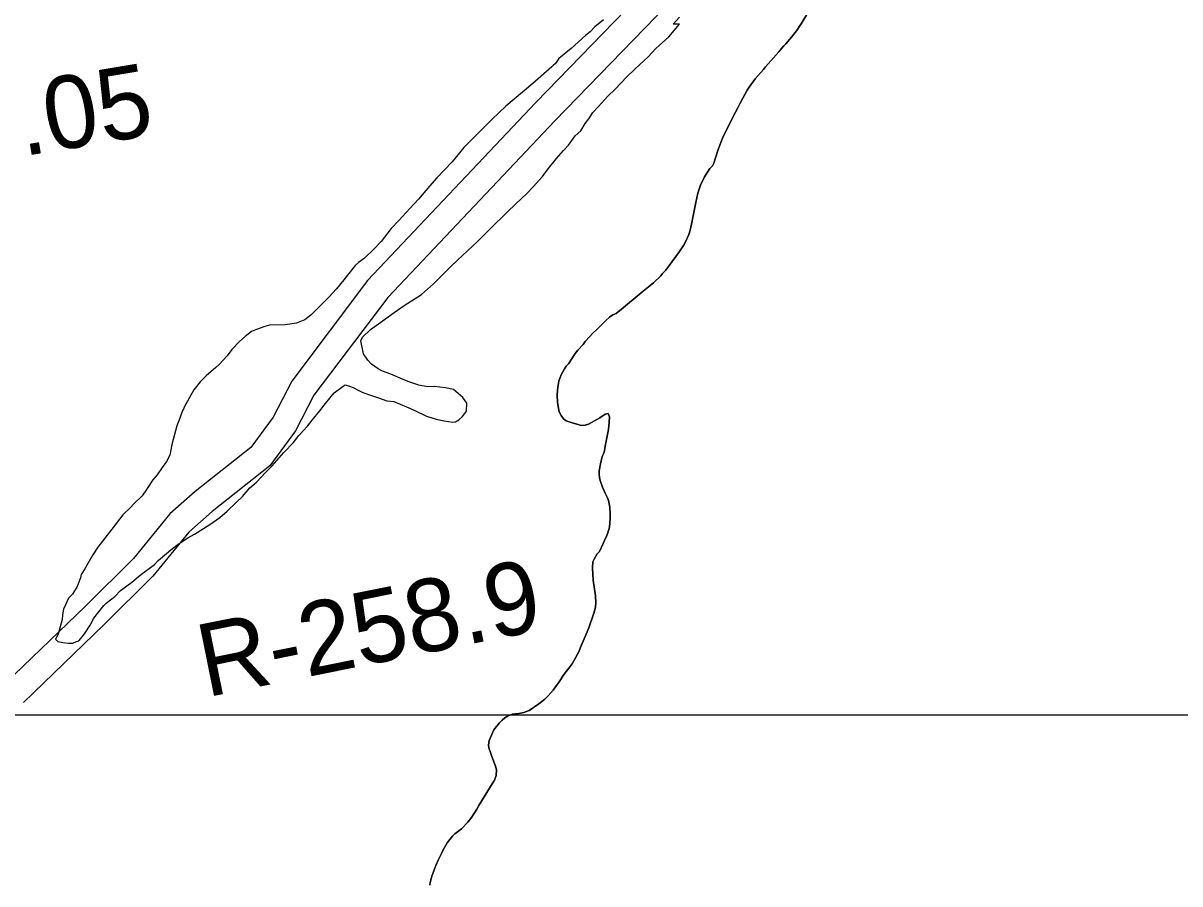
# Model space of a CAD drawing. Extents: x 3250478 to 3288318, y 788638 to 816472.
# Drawn here: x 3278390 to 3279710, y 799883 to 800865 of the extents above; entities that cross this region are included whole.
import ezdxf

# ---------------------------------------------------------------- set-up
doc = ezdxf.new("R2010")
doc.units = 0
for name, color, linetype in [('V-GRID-MAJR', 7, 'Continuous'), ('V-RIVR-RANG-IDEN', 7, 'Continuous'), ('V-ROAD-CNTR', 7, 'Continuous'), ('V-SITE-VEGE', 7, 'Continuous'), ('V-TOPO-SHOR', 7, 'Continuous')]:
    doc.layers.add(name, color=color, linetype=linetype)

msp = doc.modelspace()

# ---------------------------------------------------------------- linework, layer by layer
at = {"layer": 'V-GRID-MAJR'}
msp.add_spline([(3254640.8, 800084.8), (3259879.3, 800081.4), (3265117.8, 800078.7), (3270356.3, 800076.8), (3275594.8, 800075.6), (3280833.3, 800075.3), (3286071.8, 800075.6)], degree=3, dxfattribs=at)
at = {"layer": 'V-ROAD-CNTR'}
for points in [[(3279206.2, 801012.6), (3278974.9, 800774.4), (3278783.1, 800571.1), (3278696.4, 800456.4), (3278675.3, 800415.4), (3278649.7, 800380.5), (3278586.3, 800330.4), (3278557.4, 800304.9), (3278515.8, 800254.1), (3278461.1, 800199.6), (3278369.5, 800111.1)], [(3279227.7, 800991.7), (3278996.6, 800753.6), (3278806.1, 800551.7), (3278721.8, 800440.3), (3278700.9, 800399.6), (3278671.5, 800359.5), (3278605.6, 800307.4), (3278579.1, 800284.1), (3278538, 800233.9), (3278482.1, 800178.2), (3278390.4, 800089.5)]]:
    msp.add_lwpolyline(points, dxfattribs=at)
at = {"layer": 'V-SITE-VEGE'}
for p, q in [((3279286.7, 800878.6), (3279278, 800864.4)), ((3279052.3, 800868.7), (3279042.3, 800860.8)), ((3279126.9, 800849.3), (3279138.9, 800863.7)), ((3279131.8, 800864), (3279139.2, 800871.8)), ((3279138.9, 800863.7), (3279131.8, 800864)), ((3279278, 800864.4), (3279276.1, 800861.7)), ((3279031.8, 800850.8), (3279015.4, 800836.2)), ((3279037, 800855.2), (3279031.8, 800850.8)), ((3279042.3, 800860.8), (3279037, 800855.2)), ((3279273.8, 800857.9), (3279267, 800848.9)), ((3279276.1, 800861.7), (3279273.8, 800857.9)), ((3279015.4, 800836.2), (3279001.2, 800824.5)), ((3279112.2, 800835.9), (3279126.9, 800849.3)), ((3279255.5, 800836.2), (3279252.5, 800832.4)), ((3279258.2, 800839.2), (3279255.5, 800836.2)), ((3279260.5, 800841.4), (3279258.2, 800839.2)), ((3279267, 800848.9), (3279260.5, 800841.4)), ((3279001.2, 800824.5), (3278997.6, 800818.9)), ((3279088.5, 800813), (3279103.3, 800826.4)), ((3279103.3, 800826.4), (3279112.2, 800835.9)), ((3279252.5, 800832.4), (3279237.3, 800815)), ((3278993.4, 800815), (3278971.8, 800796)), ((3278995, 800816.7), (3278993.4, 800815)), ((3278997.6, 800818.9), (3278995, 800816.7)), ((3279078.6, 800803.5), (3279088.5, 800813)), ((3279235, 800812), (3279225.6, 800801.3)), ((3279237.3, 800815), (3279235, 800812)), ((3279066, 800790.2), (3279078.6, 800803.5)), ((3279225.6, 800801.3), (3279218.6, 800791.9)), ((3278971.8, 800796), (3278940.7, 800770.2)), ((3279057.1, 800781.8), (3279066, 800790.2)), ((3279216.5, 800788.5), (3279208.8, 800774.6)), ((3279218.6, 800791.9), (3279216.5, 800788.5)), ((3278940.7, 800770.2), (3278925, 800755.2)), ((3279046.1, 800769.6), (3279057.1, 800781.8)), ((3279208.8, 800774.6), (3279206.1, 800769)), ((3279035.7, 800755.8), (3279040.3, 800763)), ((3279040.3, 800763), (3279046.1, 800769.6)), ((3279206.1, 800769), (3279199.7, 800756.8)), ((3278925, 800755.2), (3278904.5, 800734.6)), ((3279026.4, 800742), (3279031.5, 800750.3)), ((3279031.5, 800750.3), (3279035.7, 800755.8)), ((3279194, 800745), (3279191.6, 800741)), ((3279199.7, 800756.8), (3279194, 800745)), ((3278904.5, 800734.6), (3278893, 800722.9)), ((3279012.3, 800725.9), (3279020.1, 800736.4)), ((3279020.1, 800736.4), (3279026.4, 800742)), ((3279188.4, 800734.6), (3279186.3, 800728.6)), ((3279191.6, 800741), (3279188.4, 800734.6)), ((3278893, 800722.9), (3278879.4, 800706.8)), ((3278998.7, 800710.4), (3279006.5, 800719.8)), ((3279006.5, 800719.8), (3279012.3, 800725.9)), ((3279182.8, 800719.8), (3279178.1, 800705)), ((3279186.3, 800728.6), (3279182.8, 800719.8)), ((3278879.4, 800706.8), (3278862.1, 800688.5)), ((3278989.3, 800698.8), (3278998.7, 800710.4)), ((3279178.1, 800705), (3279176.6, 800702.2)), ((3278982.6, 800689.9), (3278989.3, 800698.8)), ((3279173.8, 800699), (3279167.8, 800689.7)), ((3279176.6, 800702.2), (3279173.8, 800699)), ((3278853.8, 800679), (3278841.2, 800664.1)), ((3278862.1, 800688.5), (3278853.8, 800679)), ((3278964.8, 800670.5), (3278972.1, 800678.3)), ((3278972.1, 800678.3), (3278982.6, 800689.9)), ((3279163.2, 800680.1), (3279161.1, 800674.3)), ((3279167.8, 800689.7), (3279163.2, 800680.1)), ((3278952.2, 800658.8), (3278964.8, 800670.5)), ((3279160.2, 800670.9), (3279157.8, 800660.4)), ((3279161.1, 800674.3), (3279160.2, 800670.9)), ((3278831.3, 800653.5), (3278818.7, 800639.6)), ((3278841.2, 800664.1), (3278831.3, 800653.5)), ((3278942.2, 800649.3), (3278952.2, 800658.8)), ((3279157.8, 800660.4), (3279152.8, 800635.4)), ((3278818.7, 800639.6), (3278809.8, 800630.7)), ((3278922.8, 800630.3), (3278942.2, 800649.3)), ((3278809.8, 800630.7), (3278798.4, 800615.8)), ((3278908.6, 800615.9), (3278922.8, 800630.3)), ((3279151.1, 800628.7), (3279149.6, 800623.9)), ((3279152.8, 800635.4), (3279151.1, 800628.7)), ((3278798.4, 800615.8), (3278790.5, 800607.5)), ((3278885.5, 800594.6), (3278908.6, 800615.9)), ((3279146.4, 800616.1), (3279143.7, 800611.3)), ((3279149.6, 800623.9), (3279146.4, 800616.1)), ((3278790.5, 800607.5), (3278779.5, 800596.9)), ((3279139, 800604.2), (3279130.9, 800592.8)), ((3279143.7, 800611.3), (3279139, 800604.2)), ((3278769, 800588.5), (3278756, 800571.9)), ((3278772.6, 800591.8), (3278769, 800588.5)), ((3278779.5, 800596.9), (3278772.6, 800591.8)), ((3278858.2, 800567.4), (3278878.1, 800587.4)), ((3278878.1, 800587.4), (3278885.5, 800594.6)), ((3279130.9, 800592.8), (3279123.3, 800583.1)), ((3279117.6, 800576.7), (3279109.4, 800568.4)), ((3279119.8, 800579.3), (3279117.6, 800576.7)), ((3279123.3, 800583.1), (3279119.8, 800579.3)), ((3278747.6, 800561.9), (3278738.7, 800552.4)), ((3278756, 800571.9), (3278747.6, 800561.9)), ((3278844.5, 800555.1), (3278858.2, 800567.4)), ((3279109.4, 800568.4), (3279095.3, 800557.2)), ((3278738.7, 800552.4), (3278726.1, 800539.6)), ((3278824.9, 800542.6), (3278844.5, 800555.1)), ((3279095.3, 800557.2), (3279073, 800538.4)), ((3278726.1, 800539.6), (3278718.3, 800531.8)), ((3278795.3, 800521.7), (3278813.2, 800534.7)), ((3278813.2, 800534.7), (3278824.9, 800542.6)), ((3279066.7, 800533.7), (3279063.1, 800531.9)), ((3279073, 800538.4), (3279066.7, 800533.7)), ((3278671.1, 800520.2), (3278665.7, 800518.9)), ((3278688.9, 800520.7), (3278671.1, 800520.2)), ((3278701.8, 800522.7), (3278688.9, 800520.7)), ((3278711.4, 800526.2), (3278701.8, 800522.7)), ((3278718.3, 800531.8), (3278711.4, 800526.2)), ((3278786.3, 800515.5), (3278795.3, 800521.7)), ((3279055.1, 800525.4), (3279044.9, 800515.3)), ((3279059.2, 800529.2), (3279055.1, 800525.4)), ((3279063.1, 800531.9), (3279059.2, 800529.2)), ((3278643.4, 800507.4), (3278637, 800501.8)), ((3278650.7, 800513.1), (3278643.4, 800507.4)), ((3278656.1, 800515.4), (3278650.7, 800513.1)), ((3278665.7, 800518.9), (3278656.1, 800515.4)), ((3278775.3, 800502.2), (3278777.4, 800506.6)), ((3278777.4, 800506.6), (3278786.3, 800515.5)), ((3279036.5, 800506.8), (3279031.4, 800501.6)), ((3279040.2, 800511), (3279036.5, 800506.8)), ((3279044.9, 800515.3), (3279040.2, 800511)), ((3278637, 800501.8), (3278628.1, 800492.4)), ((3278778.5, 800487.7), (3278775.3, 800502.2)), ((3279029.1, 800498.3), (3279023.1, 800491.7)), ((3279031.4, 800501.6), (3279029.1, 800498.3)), ((3278622.9, 800485.2), (3278613.5, 800475.2)), ((3278628.1, 800492.4), (3278622.9, 800485.2)), ((3278783.5, 800480.3), (3278778.5, 800487.7)), ((3278787.5, 800475.6), (3278783.5, 800480.3)), ((3279019.9, 800487.9), (3279012.2, 800476.2)), ((3279023.1, 800491.7), (3279019.9, 800487.9)), ((3278609.8, 800471.9), (3278598.8, 800462.3)), ((3278613.5, 800475.2), (3278609.8, 800471.9)), ((3278795.2, 800470.4), (3278787.5, 800475.6)), ((3278800.1, 800467.8), (3278795.2, 800470.4)), ((3278809.4, 800464.3), (3278800.1, 800467.8)), ((3279007.9, 800470.4), (3279004, 800463.4)), ((3279009.8, 800473.4), (3279007.9, 800470.4)), ((3279012.2, 800476.2), (3279009.8, 800473.4)), ((3278592, 800455.7), (3278584.7, 800446.3)), ((3278598.8, 800462.3), (3278592, 800455.7)), ((3278823.6, 800458.3), (3278809.4, 800464.3)), ((3278832.4, 800454.8), (3278823.6, 800458.3)), ((3278841.7, 800451.8), (3278832.4, 800454.8)), ((3279001.4, 800456.8), (3278999.8, 800446.4)), ((3279002.7, 800460.4), (3279001.4, 800456.8)), ((3279004, 800463.4), (3279002.7, 800460.4)), ((3278584.7, 800446.3), (3278577.5, 800433.6)), ((3278734.8, 800430.8), (3278744.7, 800442.9)), ((3278744.7, 800442.9), (3278755.3, 800450.8)), ((3278755.3, 800450.8), (3278757.4, 800452)), ((3278757.4, 800452), (3278762.3, 800450.5)), ((3278762.3, 800450.5), (3278766.7, 800449)), ((3278766.7, 800449), (3278772.1, 800445.9)), ((3278772.1, 800445.9), (3278777.6, 800443.4)), ((3278777.6, 800443.4), (3278786.4, 800440.4)), ((3278786.4, 800440.4), (3278795.6, 800437.4)), ((3278851.4, 800449.9), (3278841.7, 800451.8)), ((3278859, 800450.1), (3278851.4, 800449.9)), ((3278872, 800448.9), (3278859, 800450.1)), ((3278881.2, 800447), (3278872, 800448.9)), ((3278891.8, 800437.6), (3278881.2, 800447)), ((3278999.8, 800446.4), (3278999.5, 800439.8)), ((3278575.4, 800430.3), (3278570.9, 800420.5)), ((3278577.5, 800433.6), (3278575.4, 800430.3)), ((3278728.6, 800422.5), (3278734.8, 800430.8)), ((3278795.6, 800437.4), (3278804.9, 800433.9)), ((3278804.9, 800433.9), (3278813.1, 800433.1)), ((3278813.1, 800433.1), (3278827.3, 800427)), ((3278827.3, 800427), (3278837.1, 800423)), ((3278896.3, 800431.3), (3278891.8, 800437.6)), ((3278896, 800422.1), (3278896.3, 800431.3)), ((3278999.5, 800439.8), (3278999.8, 800432.5)), ((3278999.8, 800432.5), (3279000.9, 800425.2)), ((3278570.9, 800420.5), (3278567.4, 800411.2)), ((3278719.7, 800411.9), (3278728.6, 800422.5)), ((3278837.1, 800423), (3278850.3, 800416.4)), ((3278850.3, 800416.4), (3278861.2, 800412.9)), ((3278887.1, 800412.1), (3278891.4, 800416)), ((3278891.4, 800416), (3278896, 800422.1)), ((3279000.9, 800425.2), (3279001.9, 800421.4)), ((3279001.9, 800421.4), (3279004, 800417.1)), ((3279004, 800417.1), (3279006.6, 800413.5)), ((3279035.2, 800407.1), (3279048, 800414.4)), ((3279048, 800414.4), (3279054.2, 800418.7)), ((3279054.2, 800418.7), (3279057.6, 800419.3)), ((3279057.6, 800419.3), (3279059.1, 800415.6)), ((3279059.1, 800415.6), (3279058.8, 800409)), ((3278565.4, 800405.2), (3278559.5, 800383.9)), ((3278567.4, 800411.2), (3278565.4, 800405.2)), ((3278704.5, 800394.2), (3278714.5, 800404.8)), ((3278714.5, 800404.8), (3278719.7, 800411.9)), ((3278861.2, 800412.9), (3278870.4, 800411.1)), ((3278870.4, 800411.1), (3278880.2, 800409.7)), ((3278880.2, 800409.7), (3278883.4, 800409.8)), ((3278883.4, 800409.8), (3278887.1, 800412.1)), ((3279006.6, 800413.5), (3279009.9, 800411.2)), ((3279009.9, 800411.2), (3279016.5, 800408.7)), ((3279016.5, 800408.7), (3279023.4, 800406.7)), ((3279023.4, 800406.7), (3279027, 800405.9)), ((3279027, 800405.9), (3279031.4, 800406)), ((3279031.4, 800406), (3279035.2, 800407.1)), ((3279057.9, 800401.3), (3279054.8, 800383.9)), ((3279058.8, 800409), (3279057.9, 800401.3)), ((3278698.3, 800386.4), (3278704.5, 800394.2)), ((3278559.5, 800383.9), (3278557.2, 800372)), ((3278674.2, 800359.8), (3278687.3, 800374.8)), ((3278687.3, 800374.8), (3278698.3, 800386.4)), ((3279053.3, 800376.8), (3279052.2, 800373.4)), ((3279053.9, 800379.9), (3279053.3, 800376.8)), ((3279054.8, 800383.9), (3279053.9, 800379.9)), ((3278553.6, 800364.8), (3278548.4, 800357.7)), ((3278557.2, 800372), (3278553.6, 800364.8)), ((3279048.8, 800361.8), (3279047.5, 800354)), ((3279050.9, 800370.2), (3279048.8, 800361.8)), ((3279052.2, 800373.4), (3279050.9, 800370.2)), ((3278542.7, 800349.4), (3278538, 800343.8)), ((3278548.4, 800357.7), (3278542.7, 800349.4)), ((3278656.4, 800340.9), (3278666.4, 800352)), ((3278666.4, 800352), (3278674.2, 800359.8)), ((3279047.5, 800354), (3279047.4, 800350)), ((3279047.4, 800350), (3279047.7, 800346.5)), ((3278538, 800343.8), (3278530.8, 800332.8)), ((3278640.2, 800324.7), (3278648.5, 800334.7)), ((3278648.5, 800334.7), (3278656.4, 800340.9)), ((3279047.7, 800346.5), (3279048.5, 800343.1)), ((3279048.5, 800343.1), (3279051.2, 800335.2)), ((3279051.2, 800335.2), (3279054.3, 800328.3)), ((3278525.6, 800325.6), (3278516.2, 800316.2)), ((3278530.8, 800332.8), (3278525.6, 800325.6)), ((3278633.4, 800318.1), (3278640.2, 800324.7)), ((3279054.3, 800328.3), (3279056.6, 800324)), ((3279056.6, 800324), (3279058.2, 800320.2)), ((3278512.5, 800312.3), (3278503.6, 800303.9)), ((3278516.2, 800316.2), (3278512.5, 800312.3)), ((3278614.4, 800300.7), (3278622.9, 800308)), ((3278622.9, 800308), (3278633.4, 800318.1)), ((3279058.2, 800320.2), (3279059.5, 800312.5)), ((3279059.5, 800312.5), (3279060.1, 800304.2)), ((3278503.6, 800303.9), (3278491.1, 800287.3)), ((3278602.8, 800292.8), (3278614.4, 800300.7)), ((3279060, 800299.6), (3279059.3, 800289.6)), ((3279060.1, 800304.2), (3279060, 800299.6)), ((3278491.1, 800287.3), (3278475, 800266.9)), ((3278585.3, 800281.5), (3278602.8, 800292.8)), ((3279057.4, 800283.3), (3279056.3, 800280.3)), ((3279059.3, 800289.6), (3279057.4, 800283.3)), ((3278558.3, 800263.9), (3278566.7, 800270.1)), ((3278566.7, 800270.1), (3278577.8, 800277.5)), ((3278577.8, 800277.5), (3278585.3, 800281.5)), ((3279051.9, 800271.2), (3279047.6, 800262)), ((3279053.6, 800274.5), (3279051.9, 800271.2)), ((3279056.3, 800280.3), (3279053.6, 800274.5)), ((3278469.3, 800258), (3278463.7, 800248.1)), ((3278475, 800266.9), (3278469.3, 800258)), ((3278544, 800251.6), (3278558.3, 800263.9)), ((3279045.1, 800259.4), (3279041.6, 800253.2)), ((3279047.6, 800262), (3279045.1, 800259.4)), ((3278460.1, 800242.1), (3278455.9, 800235.5)), ((3278463.7, 800248.1), (3278460.1, 800242.1)), ((3278523.5, 800234.8), (3278539.9, 800247.2)), ((3278539.9, 800247.2), (3278544, 800251.6)), ((3279040.3, 800250.2), (3279039.6, 800243.4)), ((3279039.6, 800243.4), (3279040.4, 800229.1)), ((3279041.6, 800253.2), (3279040.3, 800250.2)), ((3278455.5, 800231.7), (3278452.5, 800225.1)), ((3278455.9, 800235.5), (3278455.5, 800231.7)), ((3278514, 800227), (3278523.5, 800234.8)), ((3279040.4, 800229.1), (3279043.3, 800211.3)), ((3278451.5, 800221.9), (3278446.3, 800213.1)), ((3278452.5, 800225.1), (3278451.5, 800221.9)), ((3278494.5, 800210.7), (3278500.8, 800217.4)), ((3278500.8, 800217.4), (3278514, 800227)), ((3278441.6, 800208.6), (3278438.1, 800200.9)), ((3278446.3, 800213.1), (3278441.6, 800208.6)), ((3278481.8, 800200.1), (3278484.5, 800202.9)), ((3278484.5, 800202.9), (3278494.5, 800210.7)), ((3279043.6, 800203.4), (3279043.1, 800198.8)), ((3279043.3, 800211.3), (3279043.6, 800203.4)), ((3278434.6, 800189.5), (3278434.2, 800184.1)), ((3278436, 800196), (3278434.6, 800189.5)), ((3278438.1, 800200.9), (3278436, 800196)), ((3278470.4, 800185.7), (3278481.8, 800200.1)), ((3279040.9, 800190.2), (3279035.4, 800174.6)), ((3279042.4, 800195.4), (3279040.9, 800190.2)), ((3279043.1, 800198.8), (3279042.4, 800195.4)), ((3278434.2, 800184.1), (3278429.9, 800167.7)), ((3278460.6, 800169.2), (3278466.3, 800178)), ((3278466.3, 800178), (3278470.4, 800185.7)), ((3278429.9, 800167.7), (3278426.8, 800161.7)), ((3278453.3, 800159.8), (3278457.5, 800164.8)), ((3278457.5, 800164.8), (3278460.6, 800169.2)), ((3279032.5, 800167.4), (3279025.6, 800151.6)), ((3279035.4, 800174.6), (3279032.5, 800167.4)), ((3278426.8, 800161.7), (3278429.6, 800159.1)), ((3278429.6, 800159.1), (3278435, 800158.2)), ((3278435, 800158.2), (3278441.5, 800157.3)), ((3278441.5, 800157.3), (3278446.4, 800157.4)), ((3278446.4, 800157.4), (3278450.7, 800159.2)), ((3278450.7, 800159.2), (3278453.3, 800159.8)), ((3279025.6, 800151.6), (3279024.1, 800147.4)), ((3279020.4, 800140.4), (3279016.4, 800133.6)), ((3279022.7, 800144.6), (3279020.4, 800140.4)), ((3279024.1, 800147.4), (3279022.7, 800144.6)), ((3279016.4, 800133.6), (3279006.4, 800120.5)), ((3279001.8, 800113.3), (3278994.8, 800103.6)), ((3279004.1, 800116.7), (3279001.8, 800113.3)), ((3279006.4, 800120.5), (3279004.1, 800116.7)), ((3278989.1, 800097.2), (3278985.4, 800093.5)), ((3278994.8, 800103.6), (3278989.1, 800097.2)), ((3278978.6, 800087.9), (3278967.4, 800080.5)), ((3278985.4, 800093.5), (3278978.6, 800087.9)), ((3278939.7, 800071.9), (3278936.7, 800069.5)), ((3278943.4, 800074.4), (3278939.7, 800071.9)), ((3278948, 800076.1), (3278943.4, 800074.4)), ((3278955.7, 800077), (3278948, 800076.1)), ((3278961.2, 800078.3), (3278955.7, 800077)), ((3278967.4, 800080.5), (3278961.2, 800078.3)), ((3278927.2, 800058.2), (3278924.3, 800052.4)), ((3278933.8, 800066.5), (3278927.2, 800058.2)), ((3278936.7, 800069.5), (3278933.8, 800066.5)), ((3278922, 800046.2), (3278920.9, 800040.8)), ((3278924.3, 800052.4), (3278922, 800046.2)), ((3278920.9, 800040.8), (3278921.4, 800037.7)), ((3278921.4, 800037.7), (3278923.4, 800032.3)), ((3278923.4, 800032.3), (3278924.9, 800027.8)), ((3278924.9, 800027.8), (3278929.1, 800016.9)), ((3278929.8, 800006.4), (3278927.9, 800001)), ((3278929.1, 800016.9), (3278930.1, 800012.8)), ((3278930.1, 800012.8), (3278929.8, 800006.4)), ((3278925.4, 799996.6), (3278916.1, 799982)), ((3278927.9, 800001), (3278925.4, 799996.6)), ((3278916.1, 799982), (3278910.1, 799972.1)), ((3278907.8, 799967.9), (3278901.6, 799958.1)), ((3278910.1, 799972.1), (3278907.8, 799967.9)), ((3278897.5, 799952.9), (3278890.1, 799945.4)), ((3278901.6, 799958.1), (3278897.5, 799952.9)), ((3278882.8, 799939.5), (3278880.1, 799937.1)), ((3278890.1, 799945.4), (3278882.8, 799939.5)), ((3278873.9, 799929.4), (3278869.2, 799921.2)), ((3278880.1, 799937.1), (3278873.9, 799929.4)), ((3278866, 799914), (3278863.7, 799909.6)), ((3278867.3, 799917.2), (3278866, 799914)), ((3278869.2, 799921.2), (3278867.3, 799917.2)), ((3278861, 799903.4), (3278856.2, 799891.2)), ((3278863.7, 799909.6), (3278861, 799903.4)), ((3278856.2, 799891.2), (3278854.5, 799884)), ((3278854.5, 799884), (3278854, 799881))]:
    msp.add_line(p, q, dxfattribs=at)
at = {"layer": 'V-TOPO-SHOR'}
for points in [[(3279004, 800417.1), (3279001.9, 800421.4), (3279000.9, 800425.2), (3278999.8, 800432.5), (3278999.5, 800439.8), (3278999.8, 800446.4), (3279001.4, 800456.8), (3279002.7, 800460.4), (3279004, 800463.4), (3279007.9, 800470.4), (3279009.8, 800473.4), (3279012.2, 800476.2), (3279019.9, 800487.9), (3279023.1, 800491.7), (3279029.1, 800498.3), (3279031.4, 800501.6), (3279036.5, 800506.8), (3279040.2, 800511), (3279044.9, 800515.3), (3279055.1, 800525.4), (3279059.2, 800529.2), (3279063.1, 800531.9), (3279066.7, 800533.7), (3279073, 800538.4), (3279095.3, 800557.2), (3279098.4, 800559.7), (3279109.4, 800568.4), (3279117.6, 800576.7), (3279119.8, 800579.3), (3279123.3, 800583.1), (3279130.9, 800592.8), (3279139, 800604.2), (3279143.7, 800611.3), (3279146.4, 800616.1), (3279149.6, 800623.9), (3279151.1, 800628.7), (3279152.8, 800635.4), (3279157.8, 800660.4), (3279160.2, 800670.9), (3279161.1, 800674.3), (3279163.2, 800680.1), (3279167.8, 800689.7), (3279173.8, 800699), (3279176.6, 800702.2), (3279178.1, 800705), (3279182.8, 800719.8), (3279186.3, 800728.6), (3279188.4, 800734.6), (3279191.6, 800741), (3279194, 800745), (3279199.7, 800756.8), (3279206.1, 800769), (3279208.8, 800774.6), (3279216.5, 800788.5), (3279218.6, 800791.9), (3279225.6, 800801.3), (3279235, 800812), (3279237.3, 800815), (3279252.5, 800832.4), (3279255.5, 800836.2), (3279258.2, 800839.2), (3279260.5, 800841.4), (3279267, 800848.9), (3279273.8, 800857.9), (3279276.1, 800861.7), (3279278, 800864.4), (3279286.7, 800878.6)], [(3278854, 799881), (3278854.5, 799884), (3278856.2, 799891.2), (3278861, 799903.4), (3278863.7, 799909.6), (3278866, 799914), (3278867.3, 799917.2), (3278869.2, 799921.2), (3278873.9, 799929.4), (3278880.1, 799937.1), (3278882.8, 799939.5), (3278890.1, 799945.4), (3278897.5, 799952.9), (3278901.6, 799958.1), (3278907.8, 799967.9), (3278910.1, 799972.1), (3278916.1, 799982), (3278925.4, 799996.6), (3278927.9, 800001), (3278929.8, 800006.4), (3278930.1, 800012.8), (3278929.1, 800016.9), (3278924.9, 800027.8), (3278923.4, 800032.3), (3278921.4, 800037.7), (3278920.9, 800040.8), (3278922, 800046.2), (3278924.3, 800052.4), (3278927.2, 800058.2), (3278933.8, 800066.5), (3278936.7, 800069.5), (3278939.7, 800071.9), (3278943.4, 800074.4), (3278948, 800076.1), (3278955.7, 800077), (3278961.2, 800078.3), (3278967.4, 800080.5), (3278978.6, 800087.9), (3278985.4, 800093.5), (3278989.1, 800097.2), (3278994.8, 800103.6), (3279001.8, 800113.3), (3279004.1, 800116.7), (3279006.4, 800120.5), (3279016.4, 800133.6), (3279020.4, 800140.4), (3279022.7, 800144.6), (3279024.1, 800147.4), (3279025.6, 800151.6), (3279032.5, 800167.4), (3279035.4, 800174.6), (3279040.9, 800190.2), (3279042.4, 800195.4), (3279043.1, 800198.8), (3279043.6, 800203.4), (3279043.3, 800211.3), (3279040.4, 800229.1), (3279039.6, 800243.4), (3279040.3, 800250.2), (3279041.6, 800253.2), (3279045.1, 800259.4), (3279047.6, 800262), (3279051.9, 800271.2), (3279053.6, 800274.5), (3279056.3, 800280.3), (3279057.4, 800283.3), (3279059.3, 800289.6), (3279060, 800299.6), (3279060.1, 800304.2), (3279059.5, 800312.5), (3279058.2, 800320.2), (3279056.6, 800324), (3279054.3, 800328.3), (3279051.2, 800335.2), (3279048.5, 800343.1), (3279047.7, 800346.5), (3279047.4, 800350), (3279047.5, 800354), (3279048.8, 800361.8), (3279050.9, 800370.2), (3279052.2, 800373.4), (3279053.3, 800376.8), (3279053.9, 800379.9), (3279054.8, 800383.9), (3279057.9, 800401.3), (3279058.8, 800409), (3279059.1, 800415.6), (3279057.6, 800419.3), (3279054.2, 800418.7), (3279048, 800414.4), (3279035.2, 800407.1), (3279031.4, 800406), (3279027, 800405.9), (3279023.4, 800406.7), (3279016.5, 800408.7), (3279009.9, 800411.2), (3279006.6, 800413.5), (3279004, 800417.1)]]:
    msp.add_lwpolyline(points, dxfattribs=at)

# ---------------------------------------------------------------- texts
at = {"layer": 'V-RIVR-RANG-IDEN'}
for s, rotation, p in [('R-259.05', 9.4375, (3278091.4, 800663.4)), ('R-258.9', 11.4058, (3278598.8, 800095.3))]:
    msp.add_text(s, height=83, rotation=rotation, dxfattribs=at).set_placement(p)

doc.saveas('drawing.dxf')
